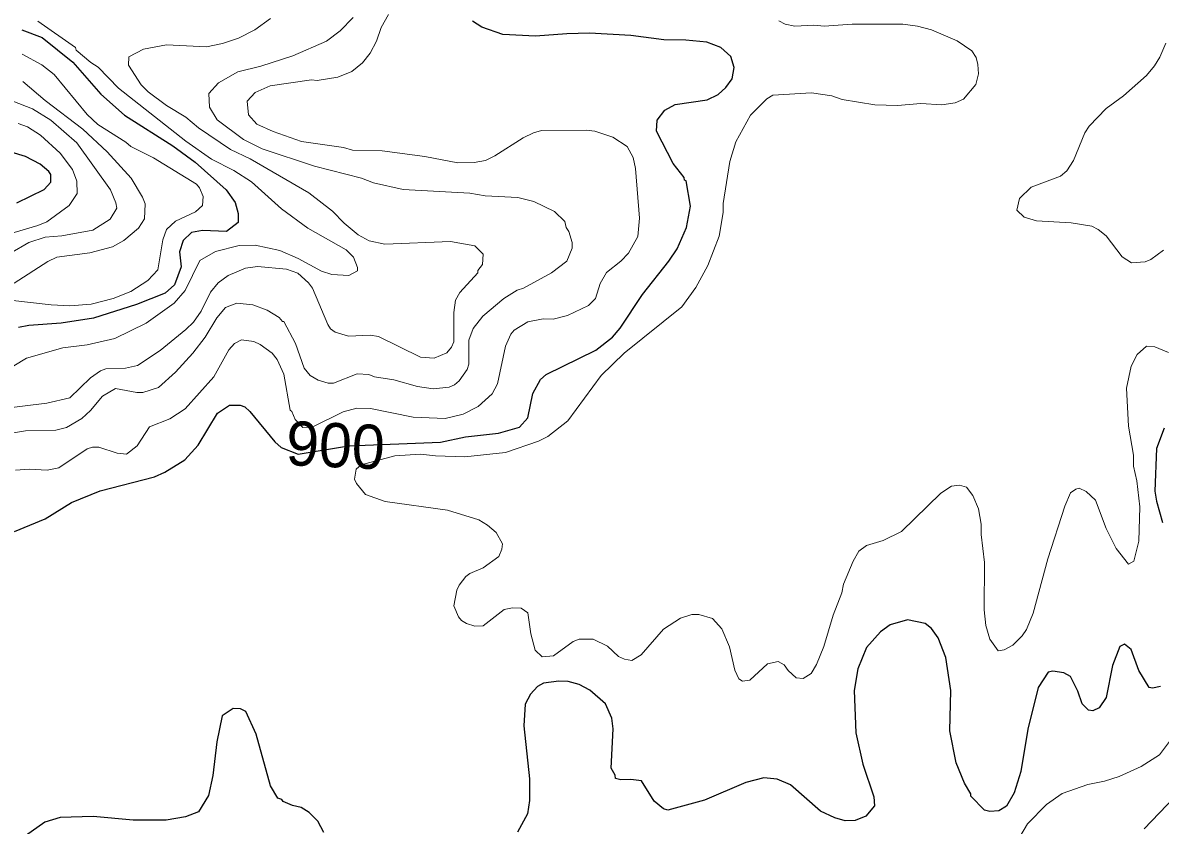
# Model space of a CAD drawing. Extents: x 598.3 to 623.2, y 6902.2 to 6930.1.
# Drawn here: x 614.707 to 616.767, y 6918.158 to 6919.612 of the extents above; entities that cross this region are included whole.
import ezdxf
from ezdxf.enums import TextEntityAlignment as Align

# ---------------------------------------------------------------- set-up
doc = ezdxf.new("R2010")
doc.units = 0
doc.header["$LTSCALE"] = 0.032
doc.layers.add('1', color=7, linetype='Continuous', lineweight=25)
doc.layers.add('2', color=7, linetype='Continuous', lineweight=13)
doc.layers.add('61', color=7, linetype='Continuous')

msp = doc.modelspace()

# ---------------------------------------------------------------- linework, layer by layer
at = {"layer": '1'}
for points in [[(615.2055, 6918.8303), (615.2968, 6918.8454), (615.4637, 6918.8521), (615.5086, 6918.862), (615.5682, 6918.8683), (615.6064, 6918.8795), (615.6219, 6918.8962), (615.6309, 6918.9403), (615.6446, 6918.9657), (615.6551, 6918.9746), (615.7445, 6919.0188), (615.775, 6919.042), (615.7889, 6919.0584), (615.8291, 6919.1196), (615.8771, 6919.1799), (615.8922, 6919.2022), (615.9091, 6919.241), (615.9163, 6919.2796), (615.9084, 6919.3252), (615.9051, 6919.3268), (615.9048, 6919.3315), (615.8849, 6919.3571), (615.8549, 6919.4157), (615.8558, 6919.4353), (615.8697, 6919.4538), (615.8886, 6919.464), (615.9464, 6919.4721), (615.9663, 6919.4816), (615.98, 6919.4947), (615.9916, 6919.5105), (615.9955, 6919.5308), (615.9895, 6919.5505), (615.9714, 6919.5673), (615.9455, 6919.5766), (615.908, 6919.5806), (615.8681, 6919.5807), (615.8082, 6919.589), (615.7332, 6919.5928), (615.6922, 6919.592), (615.6353, 6919.5873), (615.5766, 6919.5904), (615.5382, 6919.604), (615.5216, 6919.6146)], [(614.7051, 6919.5989), (614.742, 6919.585), (614.7973, 6919.5405), (614.8481, 6919.4825), (614.8909, 6919.4445), (614.9787, 6919.3891), (615.0193, 6919.3595), (615.075, 6919.309), (615.0914, 6919.2861), (615.0971, 6919.2666), (615.0968, 6919.2501), (615.0757, 6919.2335), (615.0324, 6919.2358), (615.0124, 6919.2321), (614.9976, 6919.2172), (614.9907, 6919.1969), (614.9936, 6919.1696), (614.9814, 6919.1372), (614.9648, 6919.1219), (614.9129, 6919.1016), (614.8352, 6919.0765), (614.7763, 6919.0675), (614.718, 6919.0634), (614.6992, 6919.0595)], [(614.696, 6919.2854), (614.7458, 6919.3096), (614.7579, 6919.3229), (614.7579, 6919.3367), (614.7541, 6919.3425), (614.7382, 6919.3558), (614.7119, 6919.3694), (614.6856, 6919.3776)], [(614.6922, 6918.6901), (614.7474, 6918.7129), (614.7951, 6918.7429), (614.8471, 6918.7637), (614.9456, 6918.7893), (614.9642, 6918.7978), (615.0007, 6918.8198), (615.0243, 6918.8469), (615.0598, 6918.9046), (615.0812, 6918.9193), (615.1004, 6918.9193), (615.1093, 6918.9161), (615.1184, 6918.9078), (615.1632, 6918.8525), (615.1746, 6918.8426), (615.2055, 6918.8303)], [(616.7741, 6918.8775), (616.7599, 6918.8408), (616.7574, 6918.7634), (616.7599, 6918.745), (616.7712, 6918.7062)], [(616.6043, 6918.4272), (616.5922, 6918.4344), (616.5723, 6918.4369), (616.564, 6918.4352), (616.5457, 6918.4076), (616.5274, 6918.3318), (616.5147, 6918.2555), (616.5027, 6918.2166), (616.4884, 6918.1923), (616.4745, 6918.1843), (616.4585, 6918.1828), (616.4486, 6918.1855), (616.4241, 6918.2108), (616.4238, 6918.2152), (616.4122, 6918.2344), (616.3971, 6918.271), (616.3859, 6918.3289), (616.3874, 6918.4024), (616.3789, 6918.4618), (616.3648, 6918.4976), (616.3528, 6918.5144), (616.341, 6918.5236), (616.3094, 6918.5301), (616.2777, 6918.5212), (616.2601, 6918.5087), (616.2351, 6918.4803), (616.2192, 6918.4412), (616.2127, 6918.4024), (616.2159, 6918.3257), (616.2286, 6918.2684), (616.2482, 6918.2094), (616.2497, 6918.1934), (616.2336, 6918.1747), (616.2142, 6918.1666), (616.1961, 6918.1658), (616.1777, 6918.1712), (616.1515, 6918.1833), (616.0976, 6918.2313), (616.0734, 6918.2418), (616.049, 6918.2442), (616.0167, 6918.2353), (615.9413, 6918.2032), (615.875, 6918.1853), (615.8674, 6918.1878), (615.8503, 6918.2019), (615.8272, 6918.2384), (615.8082, 6918.241), (615.7898, 6918.2403), (615.7805, 6918.2428), (615.7795, 6918.2488), (615.7723, 6918.2613), (615.7763, 6918.3328), (615.774, 6918.3522), (615.7625, 6918.3778), (615.734, 6918.4025), (615.7143, 6918.4133), (615.6945, 6918.4183), (615.678, 6918.4191), (615.6498, 6918.4157), (615.6393, 6918.4092), (615.6262, 6918.3954), (615.6168, 6918.3775), (615.6145, 6918.3382), (615.6249, 6918.2421), (615.6249, 6918.2027), (615.6213, 6918.1789), (615.6027, 6918.1457)], [(616.7673, 6918.4096), (616.7531, 6918.4062), (616.7472, 6918.4077), (616.728, 6918.4384), (616.7145, 6918.4766), (616.7023, 6918.4861), (616.6935, 6918.4821), (616.6806, 6918.4477), (616.6692, 6918.3894), (616.6564, 6918.3708), (616.6451, 6918.365), (616.6369, 6918.3665), (616.6255, 6918.3779), (616.618, 6918.4008), (616.6043, 6918.4272)], [(615.2521, 6918.145), (615.2412, 6918.1657), (615.2258, 6918.1811), (615.2108, 6918.1899), (615.1953, 6918.1935), (615.1785, 6918.2012), (615.1761, 6918.2047), (615.169, 6918.2073), (615.1554, 6918.2292), (615.1294, 6918.3231), (615.1111, 6918.3643), (615.1011, 6918.3689), (615.0877, 6918.3697), (615.068, 6918.3563), (615.0586, 6918.309), (615.0509, 6918.248), (615.0431, 6918.2118), (615.0249, 6918.1823), (615.0019, 6918.1731), (614.9667, 6918.1674), (614.907, 6918.1674), (614.8345, 6918.1738), (614.7749, 6918.1722), (614.7467, 6918.1633), (614.7116, 6918.1391)]]:
    msp.add_lwpolyline(points, dxfattribs=at)
at = {"layer": '2'}
for points in [[(614.7343, 6919.6149), (614.8023, 6919.567), (614.8034, 6919.5622), (614.8303, 6919.5398), (614.8434, 6919.5317), (614.8801, 6919.4934), (615.0022, 6919.3971), (615.0486, 6919.3647), (615.0893, 6919.3442), (615.1212, 6919.3234), (615.1754, 6919.2749), (615.2234, 6919.2395), (615.2928, 6919.2004), (615.3057, 6919.1869), (615.3131, 6919.1682), (615.3129, 6919.1627), (615.2976, 6919.1542), (615.2669, 6919.1558), (615.248, 6919.1621), (615.2059, 6919.1847), (615.1722, 6919.1992), (615.1277, 6919.2092), (615.099, 6919.2084), (615.056, 6919.1974), (615.0278, 6919.181), (615.0012, 6919.1267), (614.981, 6919.1036), (614.9304, 6919.0675), (614.8735, 6919.0399), (614.8233, 6919.0286), (614.7793, 6919.0228), (614.7135, 6919.0043), (614.6302, 6918.954)], [(614.672, 6918.8658), (614.7116, 6918.8724), (614.7669, 6918.874), (614.7861, 6918.8787), (614.8139, 6918.8949), (614.8298, 6918.9094), (614.8514, 6918.9351), (614.8751, 6918.9492), (614.9137, 6918.9421), (614.9245, 6918.9421), (614.9527, 6918.9508), (614.9834, 6918.9788), (615.0149, 6919.0134), (615.0371, 6919.0422), (615.0582, 6919.077), (615.0738, 6919.096), (615.0947, 6919.1039), (615.1233, 6919.1006), (615.1497, 6919.0913), (615.1715, 6919.0781), (615.1775, 6919.0705), (615.1799, 6919.0704), (615.2006, 6919.0306), (615.2164, 6918.9861), (615.2272, 6918.973), (615.242, 6918.9642), (615.2599, 6918.9589), (615.2698, 6918.9587), (615.3128, 6918.9761), (615.3335, 6918.9744), (615.3442, 6918.9701), (615.3791, 6918.9647), (615.4219, 6918.9531), (615.4499, 6918.9486), (615.4794, 6918.9518), (615.489, 6918.9558), (615.4973, 6918.9634), (615.5116, 6918.9835), (615.5148, 6918.9931), (615.5149, 6919.037), (615.5229, 6919.0577), (615.5401, 6919.0805), (615.5784, 6919.1123), (615.602, 6919.1273), (615.6135, 6919.1313), (615.6647, 6919.1586), (615.692, 6919.1801), (615.7018, 6919.2035), (615.7017, 6919.2138), (615.6957, 6919.234), (615.6908, 6919.2408), (615.6885, 6919.2516), (615.6702, 6919.2698), (615.6325, 6919.2878), (615.6034, 6919.295), (615.5443, 6919.2986), (615.5164, 6919.303), (615.3961, 6919.3096), (615.3422, 6919.3216), (615.3203, 6919.3306), (615.2353, 6919.3518), (615.1403, 6919.3835), (615.1068, 6919.4002), (615.0587, 6919.4362), (615.045, 6919.4592), (615.0438, 6919.4835), (615.0616, 6919.503), (615.0966, 6919.523), (615.1379, 6919.533), (615.1957, 6919.5522), (615.2569, 6919.5788), (615.2819, 6919.5971), (615.3054, 6919.6217)], [(614.9215, 6919.4996), (614.8982, 6919.5348), (614.8989, 6919.5504), (614.9258, 6919.5638), (614.9674, 6919.5718), (615.0395, 6919.5685), (615.0684, 6919.5744), (615.0974, 6919.584), (615.1269, 6919.5988), (615.1556, 6919.6197)], [(615.3692, 6919.6268), (615.356, 6919.6032), (615.3478, 6919.5786), (615.3363, 6919.5565), (615.3221, 6919.5394), (615.3029, 6919.5234), (615.2775, 6919.5133), (615.2399, 6919.5071), (615.2299, 6919.5086), (615.1552, 6919.4973), (615.128, 6919.4856), (615.1135, 6919.47), (615.1158, 6919.4451), (615.1306, 6919.4284), (615.1606, 6919.4146), (615.2119, 6919.397), (615.288, 6919.3857), (615.304, 6919.3811), (615.3578, 6919.3799), (615.4353, 6919.3695), (615.4949, 6919.3582), (615.5242, 6919.3585), (615.545, 6919.3625), (615.5621, 6919.3707), (615.6134, 6919.4033), (615.6317, 6919.4123), (615.6463, 6919.4164), (615.7275, 6919.4172), (615.7431, 6919.4155), (615.7753, 6919.4043), (615.8016, 6919.3875), (615.8125, 6919.3676), (615.8167, 6919.3479), (615.824, 6919.258), (615.8208, 6919.2249), (615.8041, 6919.1942), (615.7902, 6919.1802)], [(615.6579, 6918.8626), (615.6942, 6918.8908), (615.7545, 6918.9728), (615.796, 6919.0134), (615.9007, 6919.0973), (615.926, 6919.1323), (615.9477, 6919.1722), (615.9683, 6919.2251), (615.9754, 6919.268), (615.9755, 6919.2847), (615.9876, 6919.3608), (615.9982, 6919.3964), (616.0247, 6919.4445), (616.0544, 6919.4739), (616.0651, 6919.4804), (616.1355, 6919.4851), (616.1719, 6919.4796), (616.1908, 6919.4728), (616.2502, 6919.4629), (616.2912, 6919.4618), (616.3335, 6919.4657), (616.3716, 6919.4634), (616.3955, 6919.4665), (616.4109, 6919.4733), (616.4327, 6919.5), (616.4376, 6919.5193), (616.4369, 6919.5365), (616.4336, 6919.5489), (616.4258, 6919.5608), (616.3991, 6919.5794), (616.3527, 6919.599), (616.3273, 6919.6059), (616.3006, 6919.6091), (616.2088, 6919.6091), (616.1585, 6919.6059), (616.1398, 6919.6075), (616.1051, 6919.6057), (616.0877, 6919.6094), (616.076, 6919.6155)], [(616.7771, 6919.5751), (616.7662, 6919.5497), (616.7564, 6919.5337), (616.7418, 6919.5165), (616.7006, 6919.4793), (616.6691, 6919.4568), (616.638, 6919.4246), (616.6301, 6919.4126), (616.61, 6919.3621), (616.5979, 6919.3435), (616.5862, 6919.3337), (616.5333, 6919.3143), (616.5122, 6919.2932), (616.5073, 6919.2726), (616.5208, 6919.2598), (616.5427, 6919.2529), (616.6058, 6919.2497), (616.6428, 6919.2433), (616.6548, 6919.2373), (616.6692, 6919.226), (616.6978, 6919.1878), (616.7147, 6919.1769), (616.7395, 6919.179), (616.7498, 6919.1831), (616.773, 6919.1996)], [(614.7056, 6919.5547), (614.7415, 6919.5355), (614.7638, 6919.5182), (614.8235, 6919.4455), (614.8427, 6919.4273), (614.8934, 6919.3957), (614.9029, 6919.3875), (614.9436, 6919.3669), (615.0213, 6919.3197), (615.027, 6919.3131), (615.0339, 6919.2974), (615.0323, 6919.2807), (615.0196, 6919.2692), (614.9833, 6919.2523), (614.9669, 6919.2375), (614.9604, 6919.2184), (614.9514, 6919.1641), (614.9333, 6919.1448), (614.9023, 6919.1247), (614.8708, 6919.1121), (614.8307, 6919.1021), (614.7923, 6919.0991), (614.7583, 6919.1007), (614.6891, 6919.1087)], [(614.7068, 6919.5056), (614.7473, 6919.4712), (614.8159, 6919.4192), (614.8596, 6919.3779)], [(614.6844, 6919.1945), (614.7177, 6919.2136), (614.7474, 6919.2237), (614.7779, 6919.2261), (614.8339, 6919.2363), (614.8652, 6919.2558), (614.877, 6919.2758), (614.8754, 6919.2859), (614.8655, 6919.309), (614.8051, 6919.3943), (614.7577, 6919.4352), (614.7246, 6919.4561), (614.642, 6919.4877)], [(614.6571, 6918.9113), (614.7507, 6918.9226), (614.792, 6918.9325), (614.8298, 6918.9686), (614.8476, 6918.9815), (614.8576, 6918.9849), (614.8932, 6918.9859), (614.9148, 6918.9909), (614.9555, 6919.0182), (615.0024, 6919.0562), (615.0159, 6919.0697), (615.0302, 6919.0892), (615.0468, 6919.124), (615.0605, 6919.1408), (615.0791, 6919.154), (615.1104, 6919.1671), (615.1318, 6919.1704), (615.1845, 6919.1654), (615.2051, 6919.1584), (615.2246, 6919.1408), (615.2314, 6919.1309), (615.2591, 6919.0652), (615.2642, 6919.0576), (615.2726, 6919.0511), (615.2966, 6919.0441), (615.3363, 6919.0457), (615.3513, 6919.0432), (615.4273, 6919.0059), (615.4521, 6919.0044), (615.4751, 6919.0141), (615.4832, 6919.0239), (615.4873, 6919.0338), (615.4873, 6919.0869), (615.4904, 6919.109), (615.4985, 6919.1231), (615.5308, 6919.1588), (615.5311, 6919.163), (615.5397, 6919.1742), (615.5409, 6919.1924), (615.5256, 6919.2076), (615.4814, 6919.2156), (615.3624, 6919.2108), (615.3341, 6919.217), (615.3144, 6919.2276), (615.2889, 6919.2489), (615.2678, 6919.2706), (615.2248, 6919.304), (615.1185, 6919.3652), (615.0833, 6919.3821), (615.0252, 6919.4216), (615.0022, 6919.4411), (614.9671, 6919.4621), (614.934, 6919.487), (614.9215, 6919.4996)], [(614.6987, 6919.4294), (614.7153, 6919.4235), (614.7391, 6919.4085), (614.7745, 6919.3756), (614.7968, 6919.3459), (614.8049, 6919.3249), (614.8057, 6919.3025), (614.7908, 6919.2809), (614.7502, 6919.2514), (614.734, 6919.2446), (614.6578, 6919.2225)], [(614.8596, 6919.3779), (614.9031, 6919.3304), (614.9238, 6919.2961), (614.9287, 6919.2841), (614.9271, 6919.2564), (614.9162, 6919.2396), (614.8898, 6919.2174), (614.8694, 6919.2062), (614.8282, 6919.1953), (614.7688, 6919.1869), (614.7521, 6919.1791), (614.6914, 6919.1398)], [(615.7902, 6919.1802), (615.764, 6919.1596), (615.7524, 6919.1396), (615.7444, 6919.1124), (615.7316, 6919.0997), (615.6932, 6919.0813), (615.6676, 6919.0748), (615.6495, 6919.0757), (615.6217, 6919.0699), (615.597, 6919.0548), (615.5907, 6919.0478), (615.5813, 6919.0257), (615.5668, 6918.958), (615.5568, 6918.9394), (615.5318, 6918.9169), (615.5046, 6918.9029), (615.4717, 6918.8951), (615.4137, 6918.8974), (615.3365, 6918.9129), (615.3119, 6918.9137), (615.2869, 6918.9067), (615.2323, 6918.8799), (615.2142, 6918.8788), (615.2005, 6918.893), (615.1942, 6918.9078), (615.191, 6918.9101), (615.1798, 6918.975), (615.1675, 6919.0019), (615.1584, 6919.0134), (615.1366, 6919.0291), (615.1251, 6919.0342), (615.1029, 6919.0374), (615.0904, 6919.0308), (615.0803, 6919.0191), (615.0527, 6918.9702), (615.001, 6918.9122), (614.9731, 6918.8945), (614.9364, 6918.88), (614.9139, 6918.8454), (614.8945, 6918.8304), (614.8776, 6918.8322), (614.8446, 6918.8432), (614.8332, 6918.8432), (614.8233, 6918.8399), (614.7725, 6918.8058), (614.7513, 6918.8012), (614.719, 6918.8029), (614.694, 6918.8011)], [(616.782, 6919.0142), (616.7569, 6919.0246), (616.742, 6919.0261), (616.7254, 6919.0108), (616.7143, 6918.9896), (616.7056, 6918.9499), (616.7096, 6918.8813), (616.7185, 6918.8282), (616.7186, 6918.8083), (616.7243, 6918.782), (616.7298, 6918.7346), (616.7283, 6918.6728), (616.7189, 6918.6366), (616.7096, 6918.6313), (616.6869, 6918.6595), (616.669, 6918.6954), (616.6497, 6918.7469)], [(616.6497, 6918.7469), (616.6331, 6918.7629), (616.6201, 6918.7687), (616.6141, 6918.7671), (616.6046, 6918.76), (616.5939, 6918.7359), (616.5632, 6918.6404), (616.5367, 6918.5422), (616.5245, 6918.5128), (616.5166, 6918.5012), (616.4998, 6918.4845), (616.4844, 6918.4757), (616.4735, 6918.4741), (616.4584, 6918.4949), (616.4513, 6918.5196), (616.4481, 6918.5485), (616.4489, 6918.6342), (616.4424, 6918.6848), (616.4425, 6918.7032), (616.4376, 6918.731), (616.4278, 6918.7553), (616.4163, 6918.7707), (616.4036, 6918.7744), (616.3887, 6918.7722), (616.3696, 6918.7598), (616.2982, 6918.6901), (616.2654, 6918.6736), (616.2351, 6918.665), (616.2211, 6918.6543), (616.2108, 6918.6366), (616.1932, 6918.595), (616.19, 6918.5789), (616.1746, 6918.5384), (616.1576, 6918.4817), (616.1446, 6918.449), (616.1346, 6918.4328), (616.12, 6918.424), (616.1076, 6918.4248), (616.093, 6918.4385), (616.0859, 6918.4488), (616.075, 6918.4546), (616.0554, 6918.4504), (616.0237, 6918.4211), (616.0105, 6918.4192), (616.004, 6918.4232), (615.9967, 6918.4387), (615.9868, 6918.4812), (615.9729, 6918.514), (615.9562, 6918.5323), (615.9312, 6918.5397), (615.9187, 6918.5397), (615.898, 6918.533), (615.8672, 6918.5131), (615.8266, 6918.467), (615.81, 6918.4564), (615.7969, 6918.4589), (615.7861, 6918.464), (615.7657, 6918.4822), (615.7399, 6918.4952), (615.7143, 6918.4953), (615.704, 6918.491), (615.6679, 6918.4648), (615.6475, 6918.463), (615.6347, 6918.4751), (615.627, 6918.5046), (615.6216, 6918.5427), (615.6098, 6918.5511), (615.5939, 6918.5518), (615.5789, 6918.5486), (615.541, 6918.5193), (615.5257, 6918.5187), (615.5105, 6918.5233), (615.5013, 6918.529), (615.496, 6918.5357), (615.4875, 6918.5554), (615.493, 6918.5837), (615.4971, 6918.5928), (615.5091, 6918.6084), (615.5165, 6918.6142), (615.5405, 6918.6246), (615.5691, 6918.6451), (615.5747, 6918.6579), (615.5755, 6918.6676), (615.5645, 6918.6883), (615.5488, 6918.7016), (615.5329, 6918.7112), (615.4763, 6918.7291), (615.3635, 6918.7444), (615.3275, 6918.7572), (615.3114, 6918.7769), (615.3078, 6918.7853), (615.3108, 6918.8033), (615.3196, 6918.8108), (615.3806, 6918.8271), (615.4273, 6918.8304), (615.4544, 6918.8271), (615.5077, 6918.8254), (615.5812, 6918.8335), (615.641, 6918.8536), (615.6579, 6918.8626)], [(616.8904, 6918.3477), (616.8598, 6918.2931), (616.7925, 6918.2086), (616.7376, 6918.1515)], [(616.4769, 6918.0764), (616.5265, 6918.1606), (616.5607, 6918.1956), (616.5891, 6918.2155), (616.6359, 6918.2319), (616.6662, 6918.2378), (616.6927, 6918.2462), (616.7323, 6918.2644), (616.7655, 6918.2856), (616.7893, 6918.3172)]]:
    msp.add_lwpolyline(points, dxfattribs=at)

# ---------------------------------------------------------------- texts
at = {"layer": '61'}
msp.add_text('900', height=0.08, rotation=357.337, dxfattribs=at).set_placement((615.2714, 6918.8066), align=Align.CENTER)

doc.saveas('drawing.dxf')
